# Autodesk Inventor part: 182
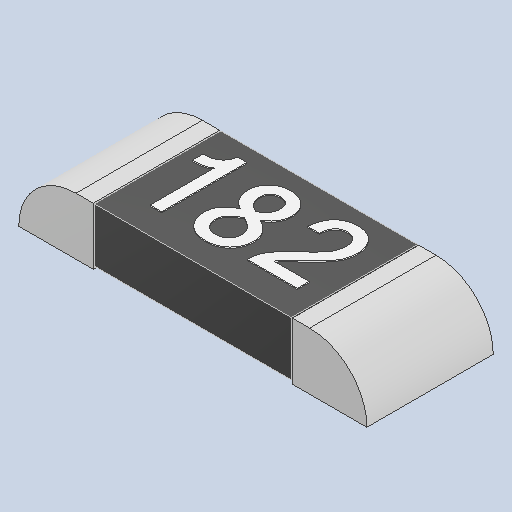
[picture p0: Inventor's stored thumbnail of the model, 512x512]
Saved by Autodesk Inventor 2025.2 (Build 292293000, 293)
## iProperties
Created: 2025-04
Part Number: 182
Material: Generic
Description: PART--DESC
Document SubType Name: Modeling
Designer: BennF
Density: 1 g/cm^3
Appearance: Default
Author: BennF
Revision Number: NONE
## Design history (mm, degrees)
feature "pin"
feature "Solid"
feature "2"
feature "1"
feature "8"
body "Solid1"
body "Solid2"
body "Solid3"
body "Solid4"
body "Solid5"
